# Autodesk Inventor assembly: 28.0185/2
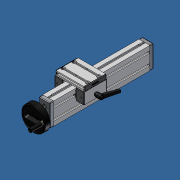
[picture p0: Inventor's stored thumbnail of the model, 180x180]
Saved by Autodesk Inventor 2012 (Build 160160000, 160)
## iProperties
Created: 2007-06
Part Number: 28.0185/2
Document SubType Name: Assembly
Designer: Andy Moles
Description: ADJUSTING UNIT VEN 45X90H WITH SIDE CLAMP
Author: Andy Moles
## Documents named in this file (24)
- C:\Andys Backup Data\ANDY'S INVENTOR\INVENTOR LIBRARIES\PARTS LIBRARY\READY FOR USE MODULES LG\28.0185_2 ADJUSTING UNIT VEN 45X90H WITH SIDE CLAMP.iam
- C:\Andys Backup Data\ANDY'S INVENTOR\INVENTOR LIBRARIES\PARTS LIBRARY\READY FOR USE MODULES LG\SUBCOMPONENTS\50.1264 BALL BEARING 10X30X9 6200 2RS DIN 625.ipt
- C:\Andys Backup Data\ANDY'S INVENTOR\INVENTOR LIBRARIES\PARTS LIBRARY\READY FOR USE MODULES LG\SUBCOMPONENTS\28.0201 BEARING PLATE 45X90 IDLER SIDE.ipt
- C:\Andys Backup Data\ANDY'S INVENTOR\INVENTOR LIBRARIES\PARTS LIBRARY\READY FOR USE MODULES LG\SUBCOMPONENTS\28.0200 BEARING PLATE 45X90 HANDWHEEL SIDE.ipt
- C:\Andys Backup Data\ANDY'S INVENTOR\INVENTOR LIBRARIES\PARTS LIBRARY\READY FOR USE MODULES LG\SUBCOMPONENTS\28.0204 HANDWHEEL 100mm.iam
- C:\Andys Backup Data\ANDY'S INVENTOR\INVENTOR LIBRARIES\PARTS LIBRARY\FASTENING ELEMENTS\NUTS\21.1351 M8 SQUARE NUT.ipt
- C:\Andys Backup Data\ANDY'S INVENTOR\INVENTOR LIBRARIES\PARTS LIBRARY\FASTENING ELEMENTS\SCREWS CAP\21.1204 M8X25.ipt
- C:\Andys Backup Data\ANDY'S INVENTOR\INVENTOR LIBRARIES\PARTS LIBRARY\READY FOR USE MODULES LG\SUBCOMPONENTS\28.0214_1 RAIL 45X90 H PROFILE.ipt
- C:\Andys Backup Data\ANDY'S INVENTOR\INVENTOR LIBRARIES\PARTS LIBRARY\FASTENING ELEMENTS\WASHERS\21.1326 DISC SPRING 20.ipt
- C:\Andys Backup Data\ANDY'S INVENTOR\INVENTOR LIBRARIES\PARTS LIBRARY\READY FOR USE MODULES LG\SUBCOMPONENTS\28.0221 ACME SCREW 16X4.ipt
- C:\Andys Backup Data\ANDY'S INVENTOR\INVENTOR LIBRARIES\PARTS LIBRARY\READY FOR USE MODULES LG\SUBCOMPONENTS\28.0126 SLIDE 45X32.ipt
- C:\Andys Backup Data\ANDY'S INVENTOR\INVENTOR LIBRARIES\PARTS LIBRARY\READY FOR USE MODULES LG\SUBCOMPONENTS\28.0126_9 SIDE LOCK 45X32.ipt
- C:\Andys Backup Data\ANDY'S INVENTOR\INVENTOR LIBRARIES\PARTS LIBRARY\READY FOR USE MODULES LG\SUBCOMPONENTS\28.0222_1 LWN 32X45-45 90X19-NSC.ipt
- 28.0222/1 SLIDE LWN 32X45-45 90X19.ipt
- C:\Andys Backup Data\ANDY'S INVENTOR\INVENTOR LIBRARIES\PARTS LIBRARY\READY FOR USE MODULES LG\SUBCOMPONENTS\28.0256 Nut slide connector 38.5.ipt
- C:\Andys Backup Data\ANDY'S INVENTOR\INVENTOR LIBRARIES\PARTS LIBRARY\READY FOR USE MODULES LG\SUBCOMPONENTS\28.0257 BRONZE NUT 16X4 NOTCHED.ipt
- C:\Andys Backup Data\ANDY'S INVENTOR\INVENTOR LIBRARIES\PARTS LIBRARY\FASTENING ELEMENTS\SCREWS CAP\21.1200 M8X16.ipt
- C:\Andys Backup Data\ANDY'S INVENTOR\INVENTOR LIBRARIES\PARTS LIBRARY\FASTENING ELEMENTS\SCREWS CAP\21.1235 M5X16.ipt
- C:\Andys Backup Data\ANDY'S INVENTOR\INVENTOR LIBRARIES\PARTS LIBRARY\COMPONENTS LG\22.1095 SLIDE RAIL LN.iam
- C:\Andys Backup Data\ANDY'S INVENTOR\INVENTOR LIBRARIES\PARTS LIBRARY\COMPONENTS LG\22.1095_9 SLIDE RAIL LN FOR SIDE LOCK.iam
- C:\Andys Backup Data\ANDY'S INVENTOR\INVENTOR LIBRARIES\PARTS LIBRARY\FASTENING ELEMENTS\NUTS\21.1330 M6 SQUARE NUT.ipt
- C:\Andys Backup Data\ANDY'S INVENTOR\INVENTOR LIBRARIES\PARTS LIBRARY\END CAPS\22.1003_1 END CAP 45x32 Z Gray.iam
- C:\Andys Backup Data\ANDY'S INVENTOR\INVENTOR LIBRARIES\PARTS LIBRARY\END CAPS\22.1014_1 END CAP 90X19 GRAY.ipt
- C:\Andys Backup Data\ANDY'S INVENTOR\INVENTOR LIBRARIES\PARTS LIBRARY\COMPONENTS LG\21.1013_1 SLIDE LOCK WITH M6X50 STUD.ipt
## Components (38 placed, 22 different names)
1. 28.0214_1 RAIL 45X90 H PROFILE:1 — Flush:9, Mate:21, Mate:22, Mate:23, Flush:10, Flush:11, Flush:12, Mate:25, Flush:13, Mate:39, Mate:40
2. 50.1264 10X30X9 6200 2RS DIN 625 BALL BEARING:1 — Insert:10
3. 50.1264 10X30X9 6200 2RS DIN 625 BALL BEARING:2 — Insert:9, Insert:13
4. 28.0201 BEARING PLATE 45X90 IDLER SIDE:1 — Insert:7, Insert:8, Insert:9, Flush:12, Mate:25, Flush:13
5. 28.0200 BEARING PLATE 45X90 HANDWHEEL SIDE:1 — Insert:3, Insert:5, Insert:6, Insert:10, Mate:23, Flush:10, Flush:11
6. 28.0204 HANDWHEEL 100mm:1 [sub-assembly] — Insert:3, Angle:7
7. 21.1204  M8 x 25:1 — Insert:5
8. 21.1204  M8 x 25:2 — Insert:6
9. 21.1204  M8 x 25:3 — Insert:8
10. 21.1204  M8 x 25:4 — Insert:7
11. 21.1326 DISC SPRING 20:1 — Insert:11
12. 21.1326 DISC SPRING 20:2 — Insert:12, Insert:13
13. 28.0221 ACME SCREW 16X4:1 — Insert:11, Insert:12, Angle:7, Mate:41
14. 28.0126 SLIDE 45X32:1 — Mate:27, Flush:14, Flush:15, Mate:33, Flush:19, Mate:34, Insert:26, Insert:29, Angle:14, Angle:17
15. 28.0126_9 SIDE LOCK 45X32:1 — Mate:30, Flush:16, Flush:17, Mate:31, Flush:18, Mate:32, Insert:27, Insert:28, Angle:15, Angle:16, Insert:30
16. 28.0222\1 SLIDE LWN 32X45-45 90X19:1 — Insert:14, Insert:15, Insert:16, Angle:8, Insert:17, Insert:18, Insert:19, Insert:20, Angle:9, Angle:10, Angle:11, Angle:12, Insert:21, Insert:22, Insert:23, Insert:24, Mate:27, Flush:14, Flush:15, Mate:30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
17. 28.0256 Nut slide connector 38.5:1 — Insert:16, Angle:8, Mate:29
18. 28.0257 BRONZE NUT 16X4 NOTCHED:1 — Mate:29, Mate:41
19. 21.1200 M8 x 16:1 — Insert:24
20. 21.1200 M8 x 16:2 — Insert:23
21. 21.1200 M8 x 16:3 — Insert:22
22. 21.1200 M8 x 16:4 — Insert:21
23. 21.1235  M5 x 16:1 — Insert:15
24. 21.1235  M5 x 16:2 — Insert:14
25. 21.1351 M8 SQUARE NUT:2 — Insert:17, Angle:12
26. 21.1351 M8 SQUARE NUT:3 — Insert:20, Angle:11
27. 21.1351 M8 SQUARE NUT:4 — Insert:19, Angle:10
28. 21.1351 M8 SQUARE NUT:5 — Insert:18, Angle:9
29. 21.1013_1 SLIDE LOCK WITH M6X50 STUD:1 — Insert:30, Angle:18, Mate:42
30. 22.1095 SLIDE RAIL LN:1 [sub-assembly] — Mate:33, Flush:19, Mate:34
31. 22.1095_9 SLIDE RAIL LN FOR SIDE LOCK:1 [sub-assembly] — Mate:31, Flush:18, Mate:32, Mate:36, Angle:13, Mate:39, Mate:40
32. 21.1330 M6 SQUARE NUT:1 — Mate:36, Angle:13, Mate:42
33. 22.1003\1 END CAP 45x32 Z Gray:1 [sub-assembly] — Insert:26, Angle:17
34. 22.1003\1 END CAP 45x32 Z Gray:2 [sub-assembly] — Insert:29, Angle:14
35. 22.1003\1 END CAP 45x32 Z Gray:3 [sub-assembly] — Insert:27, Angle:16
36. 22.1003\1 END CAP 45x32 Z Gray:4 [sub-assembly] — Insert:28, Angle:15
37. 22.1014_1 END CAP 90X19 GRAY:1 — Mate:37, Flush:20, Flush:21
38. 22.1014_1 END CAP 90X19 GRAY:2 — Mate:38, Flush:22, Flush:23
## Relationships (71: Insert 26, Mate 18, Flush 15, Angle 12)
- Insert:3: 28.0200 BEARING PLATE 45X90 HANDWHEEL SIDE:1 ↔ 28.0204 HANDWHEEL 100mm:1
- Insert:5: 28.0200 BEARING PLATE 45X90 HANDWHEEL SIDE:1 ↔ 21.1204  M8 x 25:1
- Insert:6: 28.0200 BEARING PLATE 45X90 HANDWHEEL SIDE:1 ↔ 21.1204  M8 x 25:2
- Insert:7: 28.0201 BEARING PLATE 45X90 IDLER SIDE:1 ↔ 21.1204  M8 x 25:4
- Insert:8: 28.0201 BEARING PLATE 45X90 IDLER SIDE:1 ↔ 21.1204  M8 x 25:3
- Insert:9: 50.1264 10X30X9 6200 2RS DIN 625 BALL BEARING:2 ↔ 28.0201 BEARING PLATE 45X90 IDLER SIDE:1
- Insert:10: 50.1264 10X30X9 6200 2RS DIN 625 BALL BEARING:1 ↔ 28.0200 BEARING PLATE 45X90 HANDWHEEL SIDE:1
- Flush:9: 28.0214_1 RAIL 45X90 H PROFILE:1
- Mate:21: 28.0214_1 RAIL 45X90 H PROFILE:1
- Mate:22: 28.0214_1 RAIL 45X90 H PROFILE:1
- Mate:23: 28.0214_1 RAIL 45X90 H PROFILE:1 ↔ 28.0200 BEARING PLATE 45X90 HANDWHEEL SIDE:1
- Flush:10: 28.0214_1 RAIL 45X90 H PROFILE:1 ↔ 28.0200 BEARING PLATE 45X90 HANDWHEEL SIDE:1
- Flush:11: 28.0214_1 RAIL 45X90 H PROFILE:1 ↔ 28.0200 BEARING PLATE 45X90 HANDWHEEL SIDE:1
- Flush:12: 28.0214_1 RAIL 45X90 H PROFILE:1 ↔ 28.0201 BEARING PLATE 45X90 IDLER SIDE:1
- Mate:25: 28.0214_1 RAIL 45X90 H PROFILE:1 ↔ 28.0201 BEARING PLATE 45X90 IDLER SIDE:1
- Flush:13: 28.0214_1 RAIL 45X90 H PROFILE:1 ↔ 28.0201 BEARING PLATE 45X90 IDLER SIDE:1
- Insert:11: 21.1326 DISC SPRING 20:1 ↔ 28.0221 ACME SCREW 16X4:1
- Insert:12: 21.1326 DISC SPRING 20:2 ↔ 28.0221 ACME SCREW 16X4:1
- Angle:7: 28.0204 HANDWHEEL 100mm:1 ↔ 28.0221 ACME SCREW 16X4:1
- Insert:13: 50.1264 10X30X9 6200 2RS DIN 625 BALL BEARING:2 ↔ 21.1326 DISC SPRING 20:2
- Insert:14: 28.0222\1 SLIDE LWN 32X45-45 90X19:1 ↔ 21.1235  M5 x 16:2
- Insert:15: 28.0222\1 SLIDE LWN 32X45-45 90X19:1 ↔ 21.1235  M5 x 16:1
- Insert:16: 28.0222\1 SLIDE LWN 32X45-45 90X19:1 ↔ 28.0256 Nut slide connector 38.5:1
- Angle:8: 28.0222\1 SLIDE LWN 32X45-45 90X19:1 ↔ 28.0256 Nut slide connector 38.5:1
- Insert:17: 28.0222\1 SLIDE LWN 32X45-45 90X19:1 ↔ 21.1351 M8 SQUARE NUT:2
- Insert:18: 28.0222\1 SLIDE LWN 32X45-45 90X19:1 ↔ 21.1351 M8 SQUARE NUT:5
- Insert:19: 28.0222\1 SLIDE LWN 32X45-45 90X19:1 ↔ 21.1351 M8 SQUARE NUT:4
- Insert:20: 28.0222\1 SLIDE LWN 32X45-45 90X19:1 ↔ 21.1351 M8 SQUARE NUT:3
- Angle:9: 28.0222\1 SLIDE LWN 32X45-45 90X19:1 ↔ 21.1351 M8 SQUARE NUT:5
- Angle:10: 28.0222\1 SLIDE LWN 32X45-45 90X19:1 ↔ 21.1351 M8 SQUARE NUT:4
- Angle:11: 28.0222\1 SLIDE LWN 32X45-45 90X19:1 ↔ 21.1351 M8 SQUARE NUT:3
- Angle:12: 28.0222\1 SLIDE LWN 32X45-45 90X19:1 ↔ 21.1351 M8 SQUARE NUT:2
- Insert:21: 28.0222\1 SLIDE LWN 32X45-45 90X19:1 ↔ 21.1200 M8 x 16:4
- Insert:22: 28.0222\1 SLIDE LWN 32X45-45 90X19:1 ↔ 21.1200 M8 x 16:3
- Insert:23: 28.0222\1 SLIDE LWN 32X45-45 90X19:1 ↔ 21.1200 M8 x 16:2
- Insert:24: 28.0222\1 SLIDE LWN 32X45-45 90X19:1 ↔ 21.1200 M8 x 16:1
- Mate:27: 28.0126 SLIDE 45X32:1 ↔ 28.0222\1 SLIDE LWN 32X45-45 90X19:1
- Flush:14: 28.0126 SLIDE 45X32:1 ↔ 28.0222\1 SLIDE LWN 32X45-45 90X19:1
- Flush:15: 28.0126 SLIDE 45X32:1 ↔ 28.0222\1 SLIDE LWN 32X45-45 90X19:1
- Mate:29: 28.0256 Nut slide connector 38.5:1 ↔ 28.0257 BRONZE NUT 16X4 NOTCHED:1
- Mate:30: 28.0126_9 SIDE LOCK 45X32:1 ↔ 28.0222\1 SLIDE LWN 32X45-45 90X19:1
- Flush:16: 28.0126_9 SIDE LOCK 45X32:1 ↔ 28.0222\1 SLIDE LWN 32X45-45 90X19:1
- Flush:17: 28.0126_9 SIDE LOCK 45X32:1 ↔ 28.0222\1 SLIDE LWN 32X45-45 90X19:1
- Mate:31: 28.0126_9 SIDE LOCK 45X32:1 ↔ 22.1095_9 SLIDE RAIL LN FOR SIDE LOCK:1
- Flush:18: 28.0126_9 SIDE LOCK 45X32:1 ↔ 22.1095_9 SLIDE RAIL LN FOR SIDE LOCK:1
- Mate:32: 28.0126_9 SIDE LOCK 45X32:1 ↔ 22.1095_9 SLIDE RAIL LN FOR SIDE LOCK:1
- Mate:33: 28.0126 SLIDE 45X32:1 ↔ 22.1095 SLIDE RAIL LN:1
- Flush:19: 28.0126 SLIDE 45X32:1 ↔ 22.1095 SLIDE RAIL LN:1
- Mate:34: 28.0126 SLIDE 45X32:1 ↔ 22.1095 SLIDE RAIL LN:1
- Mate:36: 22.1095_9 SLIDE RAIL LN FOR SIDE LOCK:1 ↔ 21.1330 M6 SQUARE NUT:1
- Angle:13: 22.1095_9 SLIDE RAIL LN FOR SIDE LOCK:1 ↔ 21.1330 M6 SQUARE NUT:1
- Insert:26: 28.0126 SLIDE 45X32:1 ↔ 22.1003\1 END CAP 45x32 Z Gray:1
- Insert:27: 28.0126_9 SIDE LOCK 45X32:1 ↔ 22.1003\1 END CAP 45x32 Z Gray:3
- Insert:28: 28.0126_9 SIDE LOCK 45X32:1 ↔ 22.1003\1 END CAP 45x32 Z Gray:4
- Insert:29: 28.0126 SLIDE 45X32:1 ↔ 22.1003\1 END CAP 45x32 Z Gray:2
- Angle:14: 28.0126 SLIDE 45X32:1 ↔ 22.1003\1 END CAP 45x32 Z Gray:2
- Angle:15: 28.0126_9 SIDE LOCK 45X32:1 ↔ 22.1003\1 END CAP 45x32 Z Gray:4
- Angle:16: 28.0126_9 SIDE LOCK 45X32:1 ↔ 22.1003\1 END CAP 45x32 Z Gray:3
- Angle:17: 28.0126 SLIDE 45X32:1 ↔ 22.1003\1 END CAP 45x32 Z Gray:1
- Mate:37: 28.0222\1 SLIDE LWN 32X45-45 90X19:1 ↔ 22.1014_1 END CAP 90X19 GRAY:1
- Flush:20: 28.0222\1 SLIDE LWN 32X45-45 90X19:1 ↔ 22.1014_1 END CAP 90X19 GRAY:1
- Flush:21: 28.0222\1 SLIDE LWN 32X45-45 90X19:1 ↔ 22.1014_1 END CAP 90X19 GRAY:1
- Mate:38: 28.0222\1 SLIDE LWN 32X45-45 90X19:1 ↔ 22.1014_1 END CAP 90X19 GRAY:2
- Flush:22: 28.0222\1 SLIDE LWN 32X45-45 90X19:1 ↔ 22.1014_1 END CAP 90X19 GRAY:2
- Flush:23: 28.0222\1 SLIDE LWN 32X45-45 90X19:1 ↔ 22.1014_1 END CAP 90X19 GRAY:2
- Mate:39: 28.0214_1 RAIL 45X90 H PROFILE:1 ↔ 22.1095_9 SLIDE RAIL LN FOR SIDE LOCK:1
- Mate:40: 28.0214_1 RAIL 45X90 H PROFILE:1 ↔ 22.1095_9 SLIDE RAIL LN FOR SIDE LOCK:1
- Mate:41: 28.0221 ACME SCREW 16X4:1 ↔ 28.0257 BRONZE NUT 16X4 NOTCHED:1
- Insert:30: 28.0126_9 SIDE LOCK 45X32:1 ↔ 21.1013_1 SLIDE LOCK WITH M6X50 STUD:1
- Angle:18: 28.0222\1 SLIDE LWN 32X45-45 90X19:1 ↔ 21.1013_1 SLIDE LOCK WITH M6X50 STUD:1
- Mate:42: 21.1013_1 SLIDE LOCK WITH M6X50 STUD:1 ↔ 21.1330 M6 SQUARE NUT:1
